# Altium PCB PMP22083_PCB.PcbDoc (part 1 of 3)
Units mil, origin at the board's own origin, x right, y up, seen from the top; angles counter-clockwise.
Board outline 6200 x 4200 mil, 2 copper layers (Top Layer, Bottom Layer), stack 62 mil thick; 186 components, 87 nets, 426 pads, 96 vias.
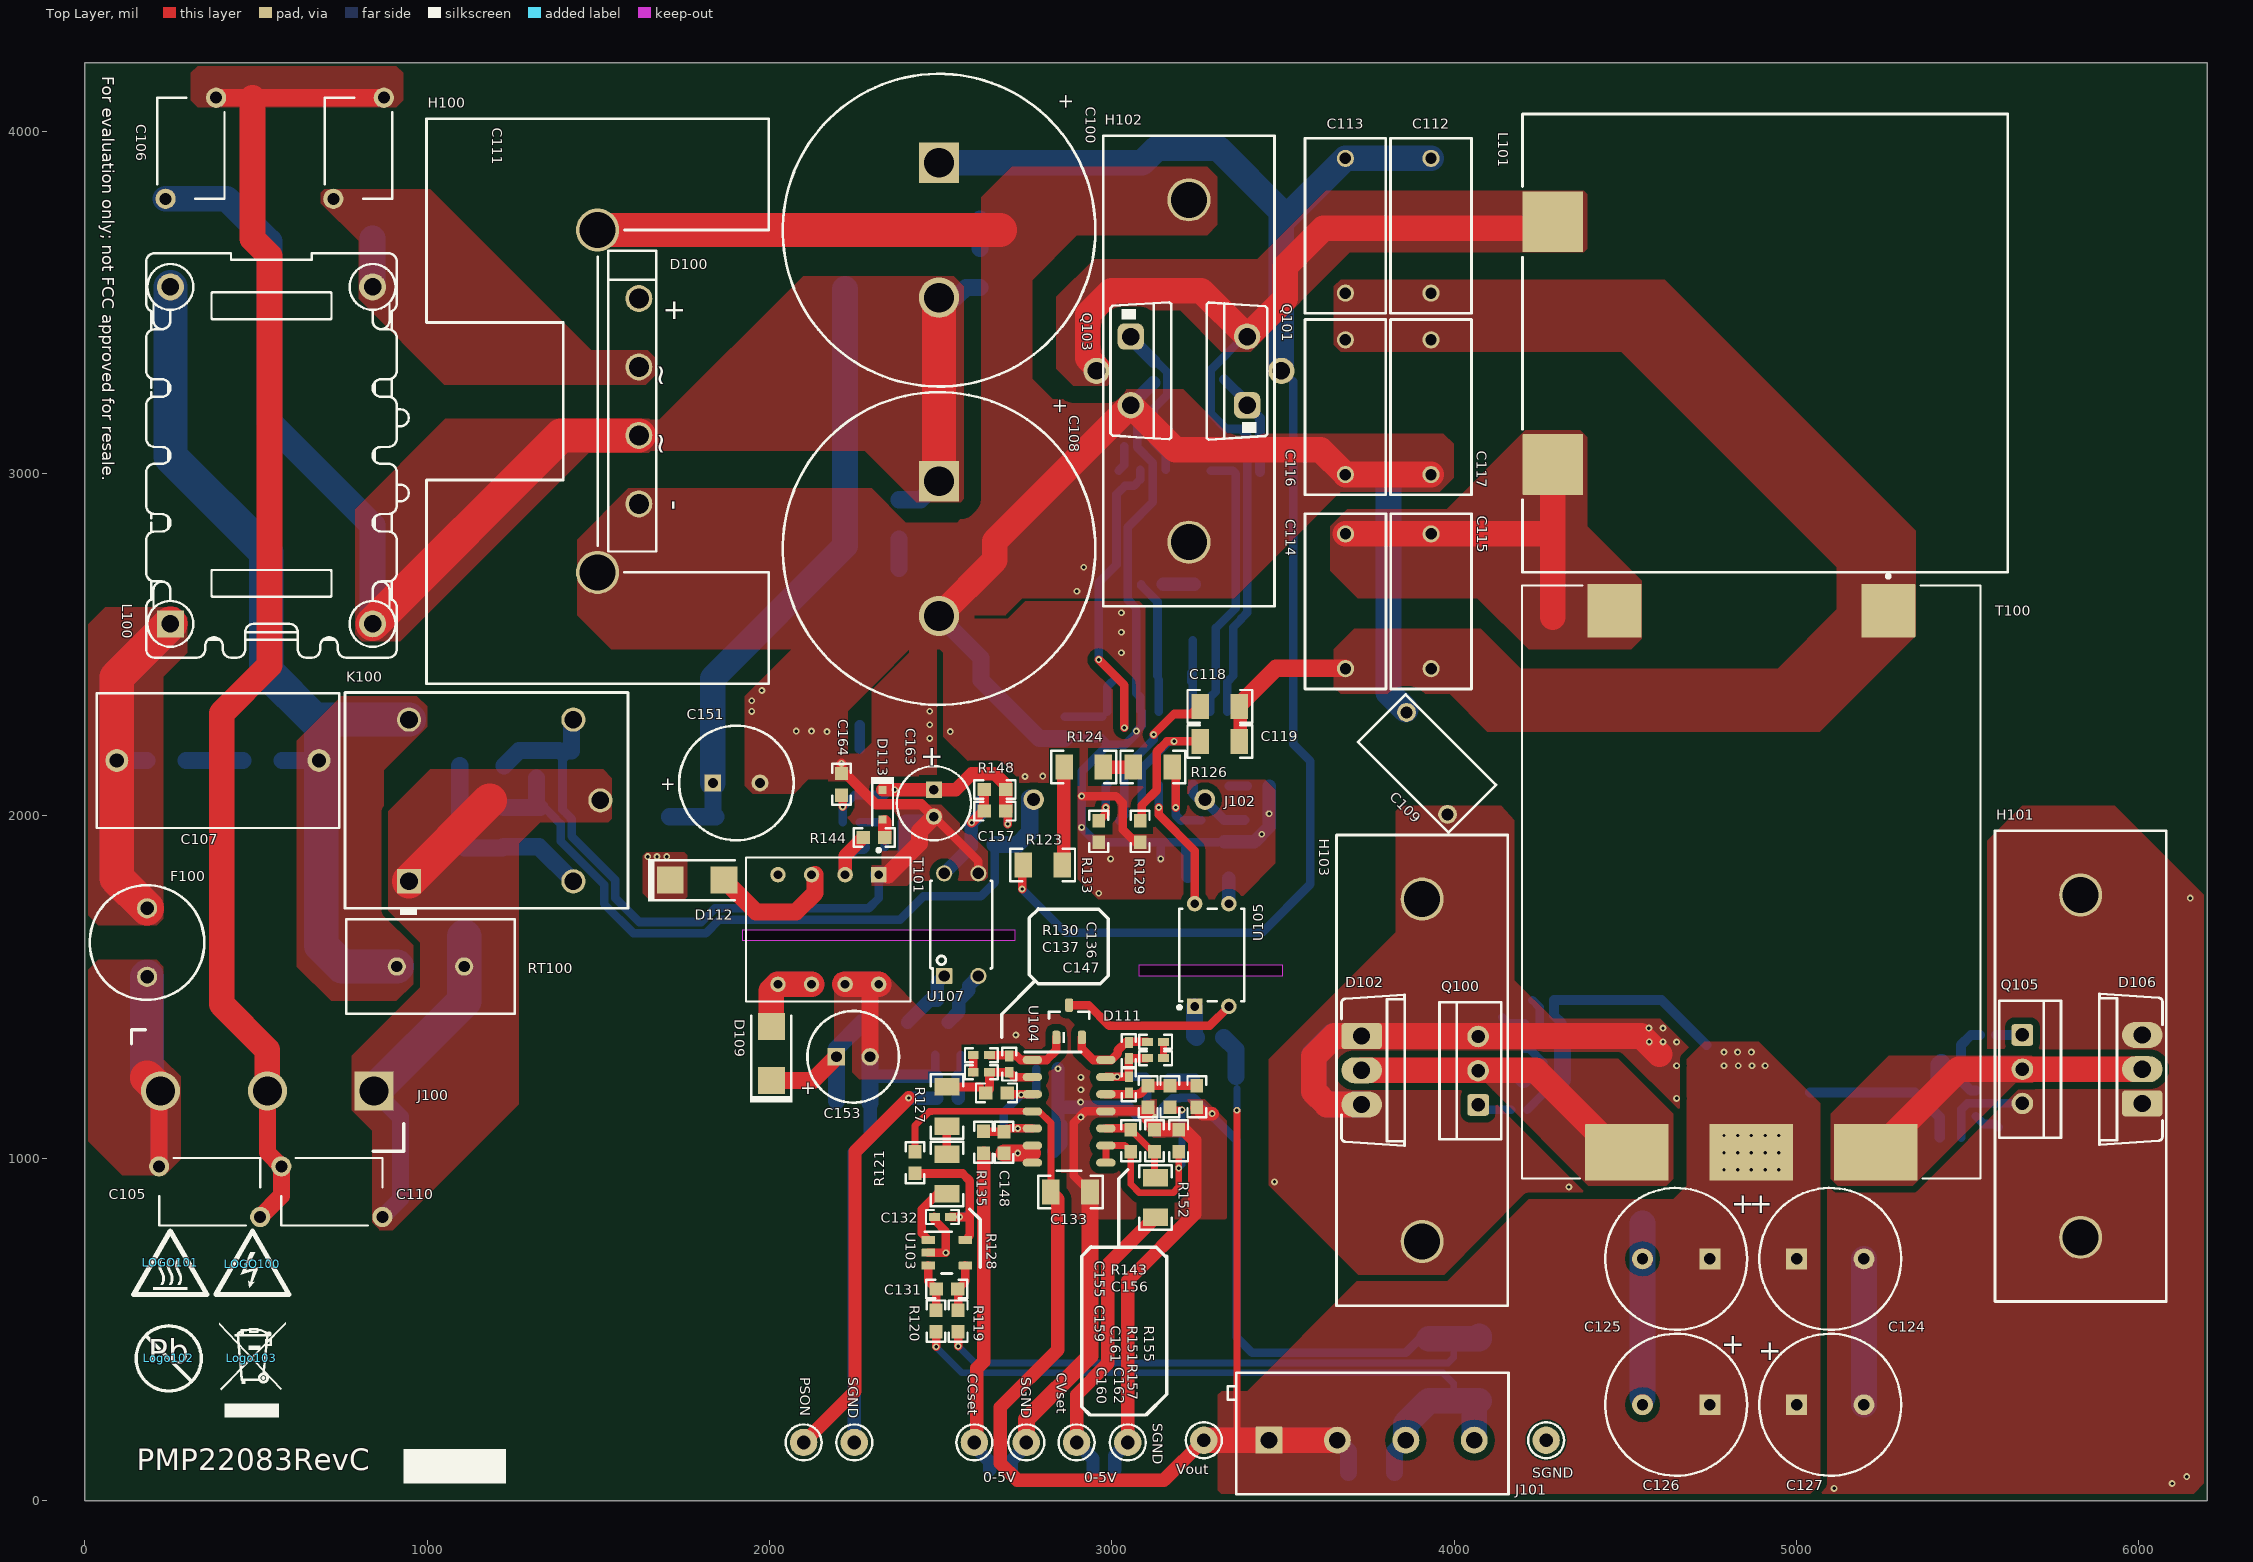
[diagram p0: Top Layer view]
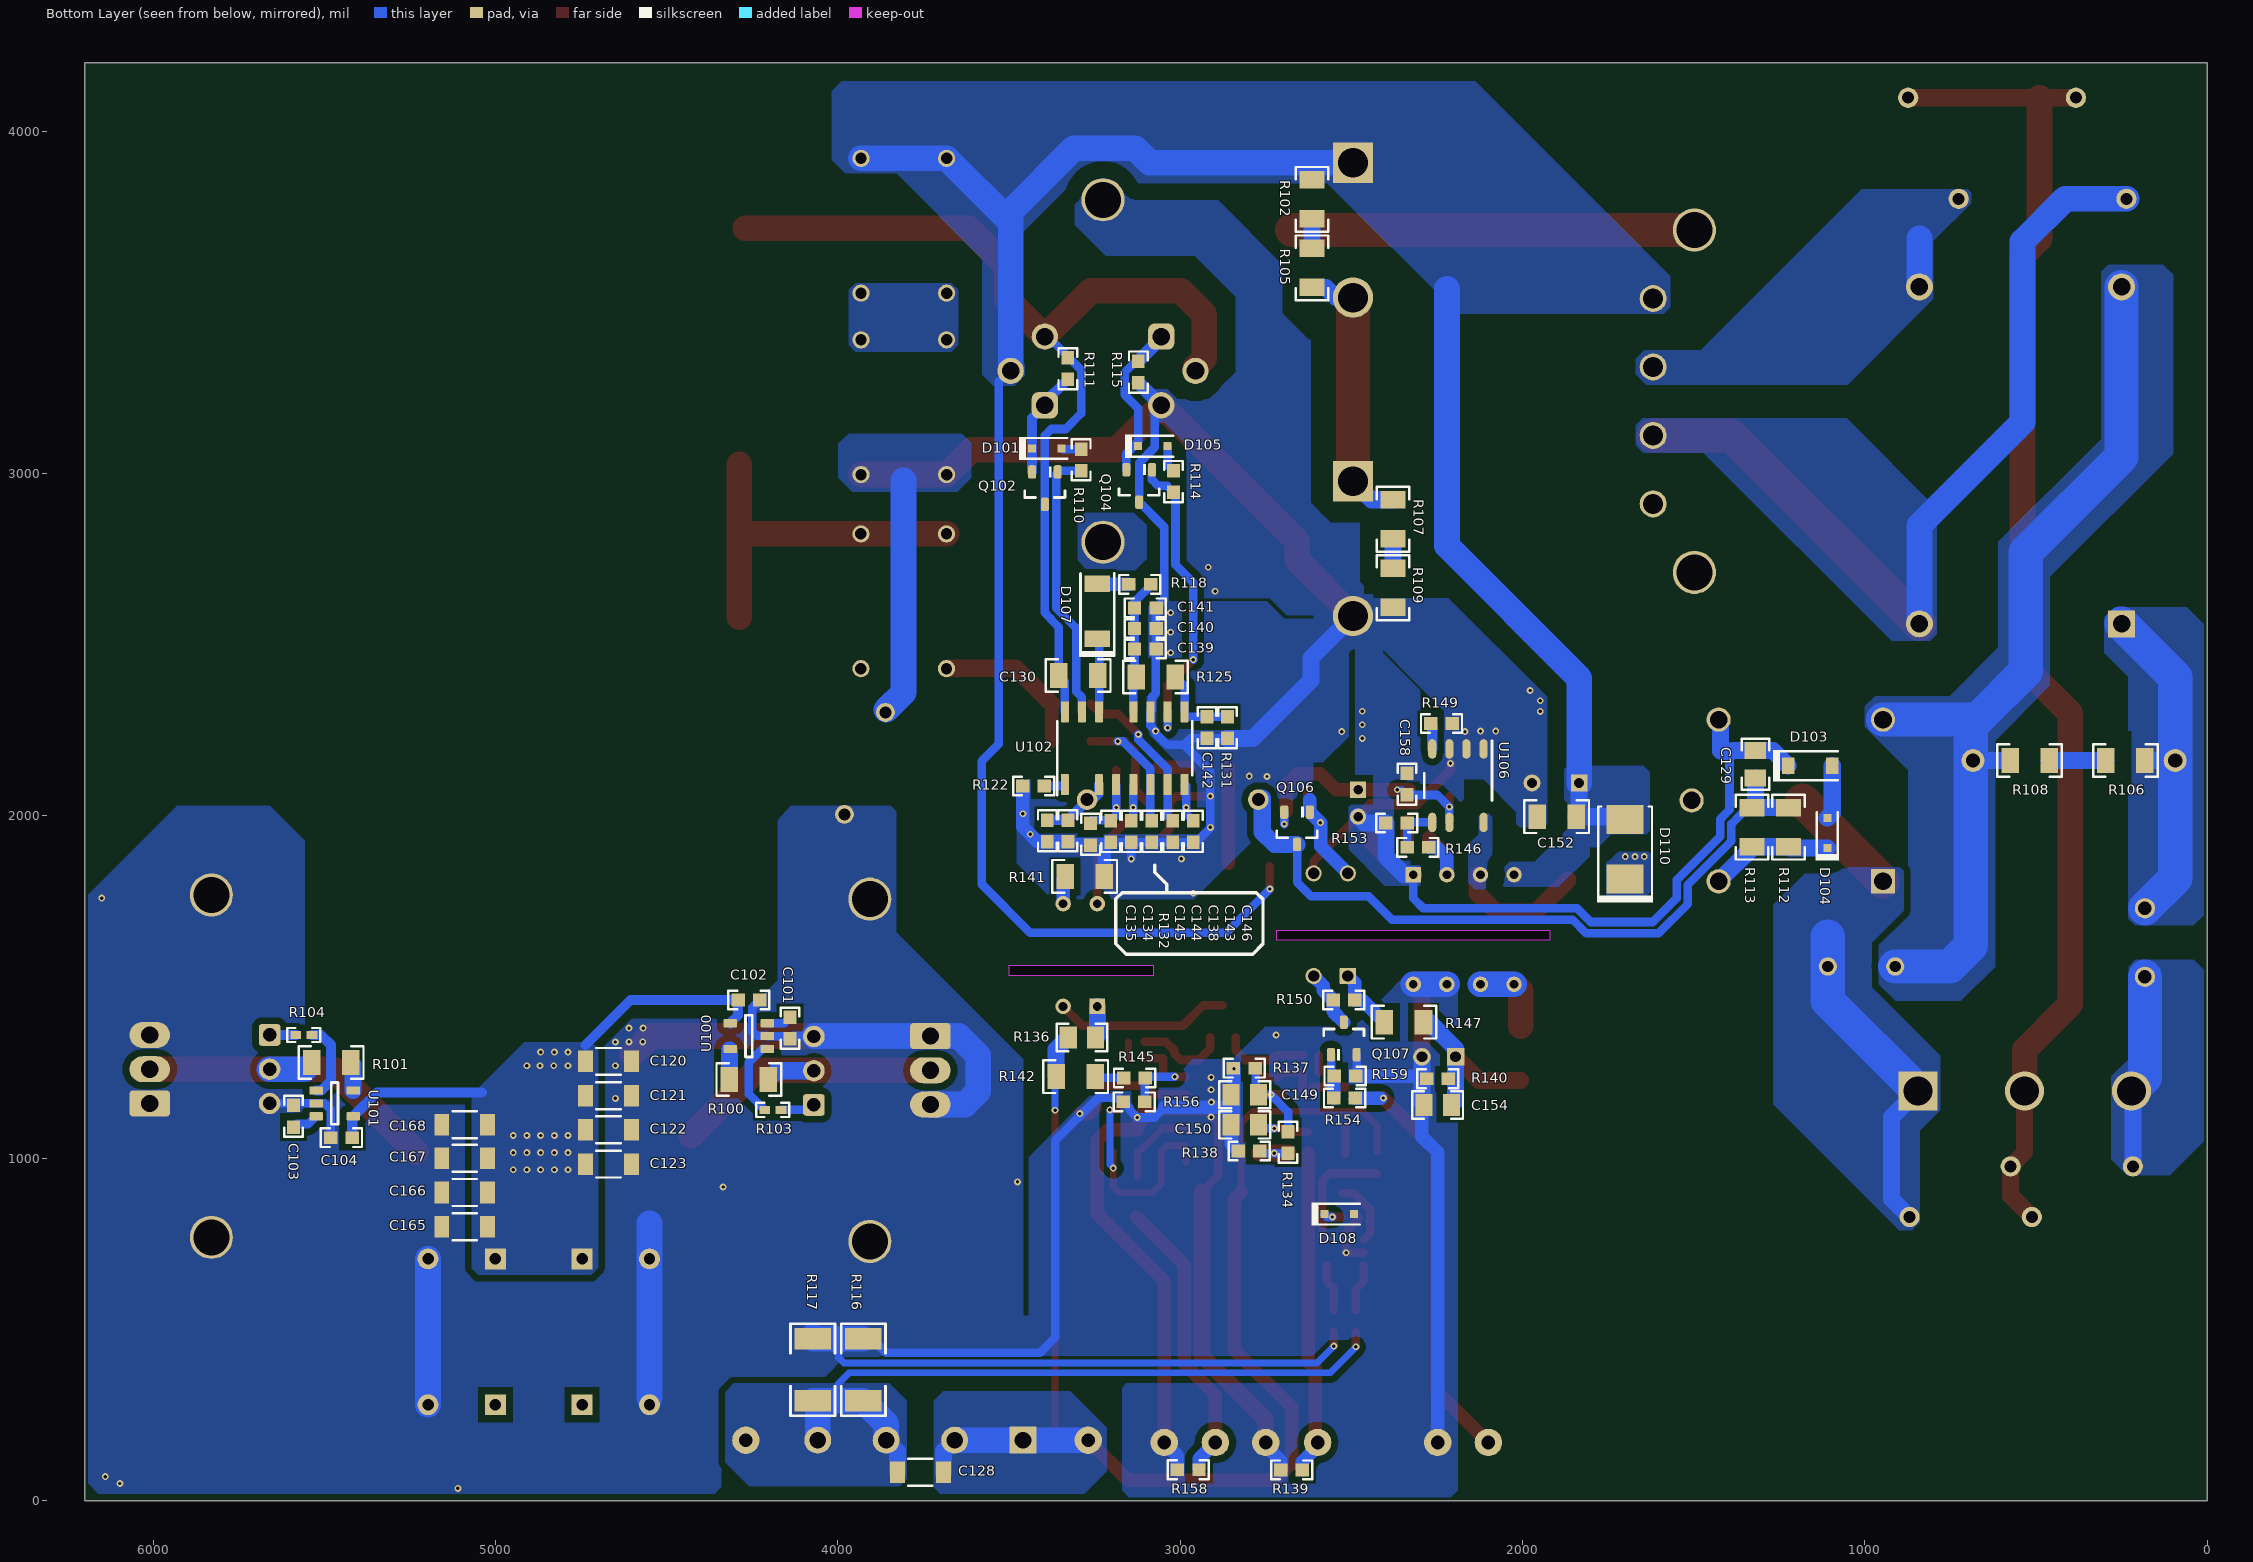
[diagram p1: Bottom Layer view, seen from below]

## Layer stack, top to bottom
Top Solder: solder mask 0.4, Solder Resist, Dk 3.5
Top Layer: signal copper 1.4
Dielectric1: core 59.2, FR-4, Dk 4.8
Bottom Layer: signal copper 1.4
Bottom Solder: solder mask 0.4, Solder Resist, Dk 3.5

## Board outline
0,0 6200,0 6200,4200 0,4200
cut-out: 1920.05,1636.33 2718.22,1636.33 2718.22,1666.33 1920.05,1666.33
cut-out: 3078.92,1533.57 3500,1533.57 3500,1563.57 3078.92,1563.57

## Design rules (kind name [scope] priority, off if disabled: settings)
AcuteAngle [All] p1: minimum=4.50000000000000E+0001 checktracksonly=FALSE
AssemblyTestPointUsage [All] p1: valid=2
Clearance Clearance_2 [InNetClass('HV') vs Not InNetClass('HV')] p1: gap=50 ignorepadtopadclearanceinfootprint=FALSE except(0: Arc-Hole Track-Hole SMDPad-Hole THPad-Hole Via-Hole Fill-Hole Poly-Hole Region-Hole Text-Hole)
Clearance Clearance_1 [InNetClass('MV') vs Not InNetClass('MV')] p2: gap=20 ignorepadtopadclearanceinfootprint=FALSE
Clearance Clearance_Keepouts [((IsTrack Or IsArc) And Not InPoly) And IsFree and IsKeepOut vs ((IsTrack Or IsArc) And Not InPoly) And IsFree and IsKeepOut] p3: gap=0 ignorepadtopadclearanceinfootprint=FALSE
Clearance Clearance_BoardEdge_MountingHoles [OnCopper and InComponentClass('Mounting Holes') vs IsKeepOut] p4: gap=40 ignorepadtopadclearanceinfootprint=FALSE except(0: Arc-Hole Track-Hole SMDPad-Hole THPad-Hole Via-Hole Fill-Hole Poly-Hole Region-Hole Text-Hole)
Clearance Clearance_BoardEdge_Poly [OnCopper and InPoly vs IsKeepOut] p5: gap=25 ignorepadtopadclearanceinfootprint=FALSE except(0: Arc-Hole Track-Hole SMDPad-Hole THPad-Hole Via-Hole Fill-Hole Poly-Hole Region-Hole Text-Hole)
Clearance Clearance_BoardEdge [OnCopper and Not InComponentClass('Logo') and not InComponentClass('FiducialMark') and not InRegion(1000,500,4000,800) and Not IsKeepout vs IsKeepOut] p6: gap=75 ignorepadtopadclearanceinfootprint=FALSE except(0: Arc-Hole Track-Hole SMDPad-Hole THPad-Hole Via-Hole Fill-Hole Poly-Hole Region-Hole Text-Hole)
Clearance Clearance_Poly [InPolygon] p7: gap=20 ignorepadtopadclearanceinfootprint=FALSE except(0: Arc-Hole Track-Hole SMDPad-Hole THPad-Hole Via-Hole Fill-Hole Poly-Hole Region-Hole Text-Hole)
Clearance [All] p8: gap=7.87 ignorepadtopadclearanceinfootprint=FALSE except(0: Arc-Hole Track-Hole SMDPad-Hole THPad-Hole Via-Hole Fill-Hole Poly-Hole Region-Hole Text-Hole)
ComponentClearance ComponentClearance_MountingHoles_FiducialMarks [InComponentClass('Mounting Holes') vs InComponentClass('FiducialMark')] p1: gap=20 collisioncheckmode=3 verticalgap=10 showdistances=FALSE
ComponentClearance ComponentClearance_Shunt [InComponentClass('Header') vs InComponentClass('Shunt')] p2: gap=0 collisioncheckmode=3 verticalgap=0 showdistances=FALSE
ComponentClearance ComponentClearance_Logo [InComponentClass('Logo')] p3: gap=5 collisioncheckmode=3 verticalgap=10 showdistances=FALSE
ComponentClearance ComponentClearance_ScrewToNut [(HasFootprint('NY PMS 440 0025 PH')) vs (HasFootprint('Keystone_1902C'))] p4: gap=20 collisioncheckmode=3 verticalgap=100000 showdistances=FALSE
ComponentClearance ComponentClearance_MountingHoles [InComponentClass('Mounting Holes')] p5: gap=20 collisioncheckmode=3 verticalgap=10 showdistances=FALSE
ComponentClearance ComponentClearance_SmallPassives [HasFootprint('0201*') or HasFootprint('0402*') or HasFootprint('0508') or HasFootprint('0603*') or HasFootprint('0612') or HasFootprint('0805*') or HasFootprint('0815*') or HasFootprint('0830*') or HasFootprint('1206*') or HasFootprint('1210*') or HasFootprint('1808*') or HasFootprint('1812*') or HasFootprint('1825*') or HasFootprint('2010*') or HasFootprint('2220*') or HasFootprint('2225*') or HasFootprint('2512*') or HasFootprint('2728*') or HasFootprint('3518*') vs HasFootprint('0201*') or HasFootprint('0402*') or HasFootprint('0508') or HasFootprint('0603*') or HasFootprint('0612') or HasFootprint('0805*') or HasFootprint('0815*') or HasFootprint('0830*') or HasFootprint('1206*') or HasFootprint('1210*') or HasFootprint('1808*') or HasFootprint('1812*') or HasFootprint('1825*') or HasFootprint('2010*') or HasFootprint('2220*') or HasFootprint('2225*') or HasFootprint('2512*') or HasFootprint('2728*') or HasFootprint('3518*')] p6: gap=20 collisioncheckmode=3 verticalgap=20 showdistances=FALSE
ComponentClearance ComponentClearance_THtoSMT [IsThruComponent vs IsSMTComponent] p7: gap=10 collisioncheckmode=3 verticalgap=10 showdistances=FALSE
ComponentClearance ComponentClearance_THtoTH [IsThruComponent vs IsThruComponent] p8: gap=10 collisioncheckmode=3 verticalgap=10 showdistances=FALSE
ComponentClearance [All] p9: gap=10 collisioncheckmode=3 verticalgap=10 showdistances=FALSE
DiffPairsRouting [All] p1: maxlimit=100 minlimit=10 mostfreqgap=10 toplayer_minwidth=15 toplayer_maxwidth=15 toplayer_prefwidth=15 bottomlayer_minwidth=15 bottomlayer_maxwidth=15 bottomlayer_prefwidth=15 maxuncoupledlength=1000
FabricationTestPointUsage TestPointUsage [All] p1: valid=2 allowmultiple=FALSE
FabricationTestpoint Testpoint [All] p1: side=3 testpointundercomponent=TRUE minsize=40 maxsize=100 preferedsize=60 minholesize=0 maxholesize=40 preferedholesize=32 testpointgrid=1 allowsidetop=TRUE allowsidebottom=TRUE usegrid=TRUE gridtolerance=0.01
FanoutControl Fanout_LCC [IsLCC] p1: bgadir=Out bgaviamode=Centered fanoutstyle=Auto fanoutdirection=Alternating viagrid=1 // Fanout_LCC (Default Rule)
FanoutControl Fanout_BGA [IsBGA] p2: bgadir=Out bgaviamode=Centered fanoutstyle=Auto fanoutdirection=Alternating viagrid=1 // Fanout_BGA (Default Rule)
FanoutControl Fanout_Default [All] p4: bgadir=Out bgaviamode=Centered fanoutstyle=Auto fanoutdirection=Alternating viagrid=1 // Fanout_Default (Default Rule)
FanoutControl Fanout_Small [(CompPinCount < 5)] p5: bgadir=Out bgaviamode=Centered fanoutstyle=Auto fanoutdirection=OutThenIn viagrid=1 // Fanout_Small (Default Rule)
Height [All] p1: minheight=0 maxheight=3000 prefheight=500
HoleSize [All] p1: absolutevalues=TRUE maxlimit=251 minlimit=7 maxpercent=80.000 minpercent=20.000
MinimumAnnularRing MinimumAnnularRing_ThermalPadVias [IsVia and InAnyComponent] p1: minimumring=5.91
MinimumAnnularRing [All] p2: minimumring=4.9
MinimumSolderMaskSliver MinimumSolderMaskSliver_Logo [InComponentClass('Logo') vs InComponentClass('Logo')] p1: minsoldermaskwidth=0.7
MinimumSolderMaskSliver [All] p2: minsoldermaskwidth=2
PlaneConnect [All] p1: planeconnectstyle=Direct reliefexpansion=10 reliefentries=4 reliefconductorwidth=10 reliefairgap=10
PolygonConnect PolygonConnect_27 [All vs IsNamedPolygon('SGND') Or  IsNamedPolygon('C110_1') Or  IsNamedPolygon('C105_2') Or  IsNamedPolygon('C105_2') Or  IsNamedPolygon('Vout') Or  IsNamedPolygon('C107_2') Or  IsNamedPolygon('C107_1') Or  IsNamedPolygon('Bottom Layer-PGND') Or  IsNamedPolygon('C124_2') Or  IsNamedPolygon('C107_1') Or  IsNamedPolygon('VD_SR2') Or  IsNamedPolygon('C100_2') Or  IsNamedPolygon('VD_SR1') Or  IsNamedPolygon('PE') Or  IsNamedPolygon('PGND') Or  IsNamedPolygon('PGND') Or  IsNamedPolygon('D110_1') Or  IsNamedPolygon('SGND') Or  IsNamedPolygon('C100_2') Or  IsNamedPolygon('PGND') Or  IsNamedPolygon('SGND') Or  IsNamedPolygon('SGND') Or  IsNamedPolygon('Vout') Or  IsNamedPolygon('C111_1') Or  IsNamedPolygon('C111_1') Or  IsNamedPolygon('C110_1') Or  IsNamedPolygon('PGND') Or  IsNamedPolygon('Vout') Or  IsNamedPolygon('D110_1') Or  IsNamedPolygon('Bottom Layer-PGND 1') Or  IsNamedPolygon('C107_2') Or  IsNamedPolygon('Vbus') Or  IsNamedPolygon('C112_2') Or  IsNamedPolygon('PGND') Or  IsNamedPolygon('C112_2') Or  IsNamedPolygon('HS') Or  IsNamedPolygon('Vbus') Or  IsNamedPolygon('C100_2') Or  IsNamedPolygon('PGND') Or  IsNamedPolygon('D108_2') Or  IsNamedPolygon('C116_1') Or  IsNamedPolygon('PGND') Or  IsNamedPolygon('PGND') Or  IsNamedPolygon('PGND')] p1: connectstyle=Direct reliefconductorwidth=10 reliefentries=4 polygonreliefangle="90 Angle" airgapwidth=10
PolygonConnect PolygonConnect_26 [All vs IsNamedPolygon('PGND') Or  IsNamedPolygon('PGND') Or  IsNamedPolygon('C124_2') Or  IsNamedPolygon('PGND') Or  IsNamedPolygon('PGND') Or  IsNamedPolygon('PGND') Or  IsNamedPolygon('SGND') Or  IsNamedPolygon('Vout') Or  IsNamedPolygon('SGND') Or  IsNamedPolygon('Bottom Layer-PGND') Or  IsNamedPolygon('SGND') Or  IsNamedPolygon('Bottom Layer-PGND 1') Or  IsNamedPolygon('Vout') Or  IsNamedPolygon('VD_SR1') Or  IsNamedPolygon('VD_SR2') Or  IsNamedPolygon('D110_1') Or  IsNamedPolygon('D110_1') Or  IsNamedPolygon('Vout') Or  IsNamedPolygon('SGND') Or  IsNamedPolygon('C107_1') Or  IsNamedPolygon('C110_1') Or  IsNamedPolygon('C110_1') Or  IsNamedPolygon('PGND') Or  IsNamedPolygon('D108_2') Or  IsNamedPolygon('C112_2') Or  IsNamedPolygon('HS') Or  IsNamedPolygon('PGND') Or  IsNamedPolygon('C100_2') Or  IsNamedPolygon('PGND') Or  IsNamedPolygon('PGND') Or  IsNamedPolygon('Vbus') Or  IsNamedPolygon('C112_2') Or  IsNamedPolygon('Vbus') Or  IsNamedPolygon('C116_1')] p2: connectstyle=Direct reliefconductorwidth=10 reliefentries=4 polygonreliefangle="90 Angle" airgapwidth=10
PolygonConnect PolygonConnect_25 [All vs IsNamedPolygon('Vout')] p3: connectstyle=Direct reliefconductorwidth=10 reliefentries=4 polygonreliefangle="90 Angle" airgapwidth=10
PolygonConnect PolygonConnect_24 [All vs IsNamedPolygon('C116_1') Or  IsNamedPolygon('PGND') Or  IsNamedPolygon('HS') Or  IsNamedPolygon('PGND') Or  IsNamedPolygon('D108_2') Or  IsNamedPolygon('C112_2') Or  IsNamedPolygon('C100_2') Or  IsNamedPolygon('Vbus') Or  IsNamedPolygon('PGND') Or  IsNamedPolygon('PGND') Or  IsNamedPolygon('PGND') Or  IsNamedPolygon('VD_SR1') Or  IsNamedPolygon('D110_1') Or  IsNamedPolygon('Bottom Layer-PGND 1') Or  IsNamedPolygon('PGND') Or  IsNamedPolygon('Vout') Or  IsNamedPolygon('VD_SR2') Or  IsNamedPolygon('PGND') Or  IsNamedPolygon('PGND') Or  IsNamedPolygon('D110_1') Or  IsNamedPolygon('Bottom Layer-PGND') Or  IsNamedPolygon('Vbus') Or  IsNamedPolygon('PGND') Or  IsNamedPolygon('C124_2') Or  IsNamedPolygon('C112_2')] p4: connectstyle=Direct reliefconductorwidth=10 reliefentries=4 polygonreliefangle="90 Angle" airgapwidth=10
PolygonConnect PolygonConnect_23 [All vs IsNamedPolygon('Bottom Layer-PGND 1') Or  IsNamedPolygon('D110_1') Or  IsNamedPolygon('D110_1') Or  IsNamedPolygon('C112_2') Or  IsNamedPolygon('D108_2') Or  IsNamedPolygon('HS') Or  IsNamedPolygon('Vbus') Or  IsNamedPolygon('C124_2') Or  IsNamedPolygon('PGND') Or  IsNamedPolygon('C100_2') Or  IsNamedPolygon('PGND') Or  IsNamedPolygon('PGND') Or  IsNamedPolygon('C112_2') Or  IsNamedPolygon('PGND') Or  IsNamedPolygon('PGND') Or  IsNamedPolygon('Bottom Layer-PGND') Or  IsNamedPolygon('PGND') Or  IsNamedPolygon('PGND') Or  IsNamedPolygon('C116_1') Or  IsNamedPolygon('PGND') Or  IsNamedPolygon('PGND') Or  IsNamedPolygon('Vbus')] p5: connectstyle=Direct reliefconductorwidth=10 reliefentries=4 polygonreliefangle="90 Angle" airgapwidth=10
PolygonConnect PolygonConnect_22 [All vs IsNamedPolygon('C116_1') Or  IsNamedPolygon('Vbus') Or  IsNamedPolygon('PGND') Or  IsNamedPolygon('SGND') Or  IsNamedPolygon('C112_2') Or  IsNamedPolygon('D108_2') Or  IsNamedPolygon('Vout') Or  IsNamedPolygon('PGND') Or  IsNamedPolygon('PGND') Or  IsNamedPolygon('PGND') Or  IsNamedPolygon('C107_2') Or  IsNamedPolygon('Vout') Or  IsNamedPolygon('PE') Or  IsNamedPolygon('C111_1') Or  IsNamedPolygon('PGND') Or  IsNamedPolygon('Vbus') Or  IsNamedPolygon('SGND') Or  IsNamedPolygon('SGND') Or  IsNamedPolygon('SGND') Or  IsNamedPolygon('PGND') Or  IsNamedPolygon('C107_2') Or  IsNamedPolygon('D105_1') Or  IsNamedPolygon('D104_1') Or  IsNamedPolygon('HS') Or  IsNamedPolygon('C100_2') Or  IsNamedPolygon('Vout') Or  IsNamedPolygon('D104_1') Or  IsNamedPolygon('D105_1') Or  IsNamedPolygon('SGND') Or  IsNamedPolygon('SGND') Or  IsNamedPolygon('C100_2') Or  IsNamedPolygon('C101_2') Or  IsNamedPolygon('PGND') Or  IsNamedPolygon('PE') Or  IsNamedPolygon('C124_2') Or  IsNamedPolygon('PGND') Or  IsNamedPolygon('C112_2') Or  IsNamedPolygon('C101_2') Or  IsNamedPolygon('PGND') Or  IsNamedPolygon('Bottom Layer-PGND') Or  IsNamedPolygon('Bottom Layer-PGND 1')] p6: connectstyle=Direct reliefconductorwidth=10 reliefentries=4 polygonreliefangle="90 Angle" airgapwidth=10
PolygonConnect PolygonConnect_21 [All vs IsNamedPolygon('SGND') Or  IsNamedPolygon('PGND') Or  IsNamedPolygon('PGND') Or  IsNamedPolygon('SGND') Or  IsNamedPolygon('SGND') Or  IsNamedPolygon('Vout') Or  IsNamedPolygon('C124_2') Or  IsNamedPolygon('PGND') Or  IsNamedPolygon('Vout') Or  IsNamedPolygon('PGND') Or  IsNamedPolygon('D105_1') Or  IsNamedPolygon('SGND') Or  IsNamedPolygon('D104_1') Or  IsNamedPolygon('Vout') Or  IsNamedPolygon('Bottom Layer-PGND') Or  IsNamedPolygon('SGND') Or  IsNamedPolygon('PGND') Or  IsNamedPolygon('PGND') Or  IsNamedPolygon('PGND') Or  IsNamedPolygon('SGND') Or  IsNamedPolygon('PGND') Or  IsNamedPolygon('C112_2') Or  IsNamedPolygon('C101_2') Or  IsNamedPolygon('C107_2') Or  IsNamedPolygon('C107_2') Or  IsNamedPolygon('D105_1') Or  IsNamedPolygon('C112_2') Or  IsNamedPolygon('Vbus') Or  IsNamedPolygon('HS') Or  IsNamedPolygon('C116_1') Or  IsNamedPolygon('PGND') Or  IsNamedPolygon('C100_2') Or  IsNamedPolygon('D108_2') Or  IsNamedPolygon('C101_2') Or  IsNamedPolygon('C100_2') Or  IsNamedPolygon('D104_1') Or  IsNamedPolygon('Vbus') Or  IsNamedPolygon('C111_1') Or  IsNamedPolygon('PE') Or  IsNamedPolygon('PE')] p7: connectstyle=Direct reliefconductorwidth=10 reliefentries=4 polygonreliefangle="90 Angle" airgapwidth=10
PolygonConnect PolygonConnect_20 [All vs IsNamedPolygon('Vout') Or  IsNamedPolygon('Vout') Or  IsNamedPolygon('Vbus') Or  IsNamedPolygon('Vout') Or  IsNamedPolygon('C101_2') Or  IsNamedPolygon('C107_2') Or  IsNamedPolygon('C124_2') Or  IsNamedPolygon('PGND') Or  IsNamedPolygon('SGND') Or  IsNamedPolygon('C112_2') Or  IsNamedPolygon('D104_1') Or  IsNamedPolygon('D105_1') Or  IsNamedPolygon('PGND') Or  IsNamedPolygon('PGND') Or  IsNamedPolygon('PGND') Or  IsNamedPolygon('HS') Or  IsNamedPolygon('C100_2') Or  IsNamedPolygon('SGND') Or  IsNamedPolygon('C100_2') Or  IsNamedPolygon('C101_2') Or  IsNamedPolygon('PE') Or  IsNamedPolygon('C116_1') Or  IsNamedPolygon('PGND') Or  IsNamedPolygon('C111_1') Or  IsNamedPolygon('D108_2') Or  IsNamedPolygon('C112_2') Or  IsNamedPolygon('C107_2') Or  IsNamedPolygon('Vbus') Or  IsNamedPolygon('PE') Or  IsNamedPolygon('D104_1') Or  IsNamedPolygon('D105_1') Or  IsNamedPolygon('PGND') Or  IsNamedPolygon('PGND') Or  IsNamedPolygon('PGND') Or  IsNamedPolygon('PGND')] p8: connectstyle=Direct reliefconductorwidth=10 reliefentries=4 polygonreliefangle="90 Angle" airgapwidth=10
PolygonConnect PolygonConnect_19 [All vs IsNamedPolygon('PE') Or  IsNamedPolygon('PE') Or  IsNamedPolygon('C101_2') Or  IsNamedPolygon('C101_2') Or  IsNamedPolygon('C107_2') Or  IsNamedPolygon('C107_2') Or  IsNamedPolygon('C100_2') Or  IsNamedPolygon('C111_1') Or  IsNamedPolygon('Vbus') Or  IsNamedPolygon('Vbus') Or  IsNamedPolygon('D108_2') Or  IsNamedPolygon('PGND')] p9: connectstyle=Direct reliefconductorwidth=10 reliefentries=4 polygonreliefangle="90 Angle" airgapwidth=10
PolygonConnect PolygonConnect_18 [All vs IsNamedPolygon('Vbus') Or  IsNamedPolygon('PGND') Or  IsNamedPolygon('Vout') Or  IsNamedPolygon('PGND') Or  IsNamedPolygon('C112_2') Or  IsNamedPolygon('C116_1') Or  IsNamedPolygon('HS') Or  IsNamedPolygon('C124_2') Or  IsNamedPolygon('5V') Or  IsNamedPolygon('C107_2') Or  IsNamedPolygon('C124_2') Or  IsNamedPolygon('PGND') Or  IsNamedPolygon('Vbus') Or  IsNamedPolygon('PGND') Or  IsNamedPolygon('C107_2') Or  IsNamedPolygon('VD_SR2') Or  IsNamedPolygon('Vout') Or  IsNamedPolygon('VD_SR_1') Or  IsNamedPolygon('C101_2') Or  IsNamedPolygon('PE') Or  IsNamedPolygon('VD_SR_1') Or  IsNamedPolygon('Vout') Or  IsNamedPolygon('C100_2') Or  IsNamedPolygon('D106_2') Or  IsNamedPolygon('VD_SR2') Or  IsNamedPolygon('PE') Or  IsNamedPolygon('PGND') Or  IsNamedPolygon('C112_2') Or  IsNamedPolygon('PE') Or  IsNamedPolygon('C100_2') Or  IsNamedPolygon('Vbus') Or  IsNamedPolygon('PE') Or  IsNamedPolygon('C101_2')] p10: connectstyle=Direct reliefconductorwidth=10 reliefentries=4 polygonreliefangle="90 Angle" airgapwidth=10
PolygonConnect PolygonConnect_17 [All vs IsNamedPolygon('PGND') Or  IsNamedPolygon('Vout') Or  IsNamedPolygon('C116_1') Or  IsNamedPolygon('C100_2') Or  IsNamedPolygon('C124_2') Or  IsNamedPolygon('C112_2') Or  IsNamedPolygon('C107_2') Or  IsNamedPolygon('PE') Or  IsNamedPolygon('HS') Or  IsNamedPolygon('Vbus') Or  IsNamedPolygon('PE') Or  IsNamedPolygon('PGND') Or  IsNamedPolygon('VD_SR_1') Or  IsNamedPolygon('VD_SR_1') Or  IsNamedPolygon('C100_2') Or  IsNamedPolygon('Vbus') Or  IsNamedPolygon('Vout') Or  IsNamedPolygon('VD_SR2') Or  IsNamedPolygon('C101_2') Or  IsNamedPolygon('C107_2') Or  IsNamedPolygon('C112_2') Or  IsNamedPolygon('VD_SR2') Or  IsNamedPolygon('C101_2')] p11: connectstyle=Direct reliefconductorwidth=10 reliefentries=4 polygonreliefangle="90 Angle" airgapwidth=10
PolygonConnect PolygonConnect_16 [All vs IsNamedPolygon('Vout') Or  IsNamedPolygon('VD_SR2') Or  IsNamedPolygon('VD_SR_1') Or  IsNamedPolygon('PE') Or  IsNamedPolygon('VD_SR2') Or  IsNamedPolygon('VD_SR_1') Or  IsNamedPolygon('C112_2')] p12: connectstyle=Direct reliefconductorwidth=10 reliefentries=4 polygonreliefangle="90 Angle" airgapwidth=10
PolygonConnect PolygonConnect_15 [All vs IsNamedPolygon('C109_2') Or  IsNamedPolygon('C107_2') Or  IsNamedPolygon('HV') Or  IsNamedPolygon('Q203_5') Or  IsNamedPolygon('C107_2') Or  IsNamedPolygon('HS') Or  IsNamedPolygon('Q201_5') Or  IsNamedPolygon('Q203_5') Or  IsNamedPolygon('C106_2') Or  IsNamedPolygon('C108_2') Or  IsNamedPolygon('Vout') Or  IsNamedPolygon('Q203_5') Or  IsNamedPolygon('C108_2') Or  IsNamedPolygon('C113_2') Or  IsNamedPolygon('Q203_5') Or  IsNamedPolygon('Q201_5') Or  IsNamedPolygon('C107_2') Or  IsNamedPolygon('C102_1') Or  IsNamedPolygon('PE') Or  IsNamedPolygon('GND') Or  IsNamedPolygon('PE') Or  IsNamedPolygon('GND') Or  IsNamedPolygon('IN+') Or  IsNamedPolygon('IN+') Or  IsNamedPolygon('Q201_5') Or  IsNamedPolygon('Q201_5') Or  IsNamedPolygon('PE') Or  IsNamedPolygon('PE') Or  IsNamedPolygon('Vout') Or  IsNamedPolygon('Vout') Or  IsNamedPolygon('IN+') Or  IsNamedPolygon('GND') Or  IsNamedPolygon('IN+') Or  IsNamedPolygon('GND')] p13: connectstyle=Direct reliefconductorwidth=10 reliefentries=4 polygonreliefangle="90 Angle" airgapwidth=10
PolygonConnect PolygonConnect_14 [All vs IsNamedPolygon('C106_2') Or  IsNamedPolygon('C107_2') Or  IsNamedPolygon('C107_2') Or  IsNamedPolygon('C107_2') Or  IsNamedPolygon('C102_1') Or  IsNamedPolygon('Q203_5') Or  IsNamedPolygon('Vout') Or  IsNamedPolygon('Q203_5') Or  IsNamedPolygon('Q203_5') Or  IsNamedPolygon('Q201_5') Or  IsNamedPolygon('C108_2') Or  IsNamedPolygon('Q203_5') Or  IsNamedPolygon('HS') Or  IsNamedPolygon('HV') Or  IsNamedPolygon('C108_2') Or  IsNamedPolygon('Q201_5') Or  IsNamedPolygon('C109_2') Or  IsNamedPolygon('Q201_5') Or  IsNamedPolygon('Q201_5') Or  IsNamedPolygon('C113_2')] p14: connectstyle=Direct reliefconductorwidth=10 reliefentries=4 polygonreliefangle="90 Angle" airgapwidth=10
PolygonConnect PolygonConnect_13 [All vs IsNamedPolygon('C102_1') Or  IsNamedPolygon('HV') Or  IsNamedPolygon('C107_2') Or  IsNamedPolygon('C109_2') Or  IsNamedPolygon('C107_2') Or  IsNamedPolygon('C108_2') Or  IsNamedPolygon('C106_2') Or  IsNamedPolygon('C108_2') Or  IsNamedPolygon('C113_2') Or  IsNamedPolygon('C107_2')] p15: connectstyle=Direct reliefconductorwidth=10 reliefentries=4 polygonreliefangle="90 Angle" airgapwidth=10
PolygonConnect PolygonConnect_12 [All vs IsNamedPolygon('C107_2') Or  IsNamedPolygon('C113_2') Or  IsNamedPolygon('C106_2') Or  IsNamedPolygon('C107_2') Or  IsNamedPolygon('C107_2') Or  IsNamedPolygon('C102_1')] p16: connectstyle=Direct reliefconductorwidth=10 reliefentries=4 polygonreliefangle="90 Angle" airgapwidth=10
PolygonConnect PolygonConnect_11 [All vs IsNamedPolygon('C106_2') Or  IsNamedPolygon('C102_1') Or  IsNamedPolygon('C107_2') Or  IsNamedPolygon('C107_2') Or  IsNamedPolygon('C107_2')] p17: connectstyle=Direct reliefconductorwidth=10 reliefentries=4 polygonreliefangle="90 Angle" airgapwidth=10
PolygonConnect PolygonConnect_10 [All vs IsNamedPolygon('C106_2')] p18: connectstyle=Direct reliefconductorwidth=10 reliefentries=4 polygonreliefangle="90 Angle" airgapwidth=10
PolygonConnect PolygonConnect_9 [All vs IsNamedPolygon('C11_1') Or  IsNamedPolygon('Vin') Or  IsNamedPolygon('Vin') Or  IsNamedPolygon('5V') Or  IsNamedPolygon('D6_2') Or  IsNamedPolygon('Q3_3') Or  IsNamedPolygon('GND2') Or  IsNamedPolygon('GND2') Or  IsNamedPolygon('GND') Or  IsNamedPolygon('Q3_4') Or  IsNamedPolygon('12V5') Or  IsNamedPolygon('GND') Or  IsNamedPolygon('12V5') Or  IsNamedPolygon('D3_1')] p19: connectstyle=Direct reliefconductorwidth=10 reliefentries=4 polygonreliefangle="90 Angle" airgapwidth=10
PolygonConnect PolygonConnect_8 [All vs IsNamedPolygon('C11_1') Or  IsNamedPolygon('Vin') Or  IsNamedPolygon('12V5') Or  IsNamedPolygon('Q3_3') Or  IsNamedPolygon('GND2') Or  IsNamedPolygon('GND2') Or  IsNamedPolygon('5V') Or  IsNamedPolygon('Q3_4') Or  IsNamedPolygon('12V5')] p20: connectstyle=Direct reliefconductorwidth=10 reliefentries=4 polygonreliefangle="90 Angle" airgapwidth=10
PolygonConnect PolygonConnect_7 [All vs IsNamedPolygon('GND2') Or  IsNamedPolygon('GND2') Or  IsNamedPolygon('5V') Or  IsNamedPolygon('12V5') Or  IsNamedPolygon('12V5') Or  IsNamedPolygon('C11_1')] p21: connectstyle=Direct reliefconductorwidth=10 reliefentries=4 polygonreliefangle="90 Angle" airgapwidth=10
PolygonConnect PolygonConnect_6 [All vs IsNamedPolygon('GND2') Or  IsNamedPolygon('PE') Or  IsNamedPolygon('GND1') Or  IsNamedPolygon('C901_1') Or  IsNamedPolygon('PE') Or  IsNamedPolygon('GND2') Or  IsNamedPolygon('GND1')] p22: connectstyle=Direct reliefconductorwidth=10 reliefentries=4 polygonreliefangle="90 Angle" airgapwidth=10
PolygonConnect PolygonConnect_5 [All vs IsNamedPolygon('GND1') Or  IsNamedPolygon('GND1')] p23: connectstyle=Direct reliefconductorwidth=10 reliefentries=4 polygonreliefangle="90 Angle" airgapwidth=10
PolygonConnect PolygonConnect_4 [All vs IsNamedPolygon('C21_1') Or  IsNamedPolygon('C5_1') Or  IsNamedPolygon('C12_2') Or  IsNamedPolygon('C2_2') Or  IsNamedPolygon('C13_1') Or  IsNamedPolygon('C28_1') Or  IsNamedPolygon('C6_1') Or  IsNamedPolygon('GND') Or  IsNamedPolygon('GND2') Or  IsNamedPolygon('C14_1') Or  IsNamedPolygon('C13_1') Or  IsNamedPolygon('Q1_3') Or  IsNamedPolygon('C14_1') Or  IsNamedPolygon('C5_1') Or  IsNamedPolygon('GND2') Or  IsNamedPolygon('C28_1') Or  IsNamedPolygon('D5_2') Or  IsNamedPolygon('D6_2') Or  IsNamedPolygon('D2_1') Or  IsNamedPolygon('C12_2') Or  IsNamedPolygon('D2_1') Or  IsNamedPolygon('C4_1') Or  IsNamedPolygon('C4_1') Or  IsNamedPolygon('C2_2') Or  IsNamedPolygon('GND') Or  IsNamedPolygon('C33_1') Or  IsNamedPolygon('C9_1')] p24: connectstyle=Direct reliefconductorwidth=10 reliefentries=4 polygonreliefangle="90 Angle" airgapwidth=10
PolygonConnect PolygonConnect_3 [All vs IsNamedPolygon('C28_1') Or  IsNamedPolygon('C12_2') Or  IsNamedPolygon('C28_1') Or  IsNamedPolygon('C9_1') Or  IsNamedPolygon('D5_2') Or  IsNamedPolygon('C12_2') Or  IsNamedPolygon('C2_2') Or  IsNamedPolygon('C14_1') Or  IsNamedPolygon('C4_1') Or  IsNamedPolygon('C14_1') Or  IsNamedPolygon('D6_2') Or  IsNamedPolygon('GND2') Or  IsNamedPolygon('Q1_3') Or  IsNamedPolygon('C5_1') Or  IsNamedPolygon('D2_1') Or  IsNamedPolygon('C4_1') Or  IsNamedPolygon('C13_1') Or  IsNamedPolygon('C5_1') Or  IsNamedPolygon('C13_1') Or  IsNamedPolygon('C33_1') Or  IsNamedPolygon('D2_1') Or  IsNamedPolygon('GND') Or  IsNamedPolygon('GND') Or  IsNamedPolygon('GND2') Or  IsNamedPolygon('C2_2') Or  IsNamedPolygon('C6_1') Or  IsNamedPolygon('C21_1')] p25: connectstyle=Direct reliefconductorwidth=10 reliefentries=4 polygonreliefangle="90 Angle" airgapwidth=10
PolygonConnect PolygonConnect_2 [All vs IsNamedPolygon('C21_1') Or  IsNamedPolygon('C4_1') Or  IsNamedPolygon('D5_2') Or  IsNamedPolygon('C5_1') Or  IsNamedPolygon('C14_1') Or  IsNamedPolygon('C13_1') Or  IsNamedPolygon('C4_1') Or  IsNamedPolygon('C33_1') Or  IsNamedPolygon('C12_2') Or  IsNamedPolygon('D2_1') Or  IsNamedPolygon('C2_2') Or  IsNamedPolygon('C28_1') Or  IsNamedPolygon('C12_2') Or  IsNamedPolygon('D2_1') Or  IsNamedPolygon('C5_1') Or  IsNamedPolygon('Q1_3') Or  IsNamedPolygon('GND') Or  IsNamedPolygon('D6_2') Or  IsNamedPolygon('C6_1') Or  IsNamedPolygon('C2_2') Or  IsNamedPolygon('C14_1') Or  IsNamedPolygon('C28_1') Or  IsNamedPolygon('C13_1') Or  IsNamedPolygon('C9_1') Or  IsNamedPolygon('GND')] p26: connectstyle=Direct reliefconductorwidth=10 reliefentries=4 polygonreliefangle="90 Angle" airgapwidth=10
PolygonConnect PolygonConnect_1 [All vs IsNamedPolygon('C28_1') Or  IsNamedPolygon('D5_2') Or  IsNamedPolygon('C5_1') Or  IsNamedPolygon('C5_1') Or  IsNamedPolygon('D2_1') Or  IsNamedPolygon('C21_1') Or  IsNamedPolygon('C9_1') Or  IsNamedPolygon('C4_1') Or  IsNamedPolygon('C14_1') Or  IsNamedPolygon('C28_1') Or  IsNamedPolygon('C6_1') Or  IsNamedPolygon('C12_2') Or  IsNamedPolygon('C33_1') Or  IsNamedPolygon('C4_1') Or  IsNamedPolygon('C13_1') Or  IsNamedPolygon('C12_2') Or  IsNamedPolygon('D6_2') Or  IsNamedPolygon('C2_2') Or  IsNamedPolygon('C14_1') Or  IsNamedPolygon('D2_1') Or  IsNamedPolygon('C2_2') Or  IsNamedPolygon('C13_1')] p27: connectstyle=Direct reliefconductorwidth=10 reliefentries=4 polygonreliefangle="90 Angle" airgapwidth=10
PolygonConnect [All] p28: connectstyle=Relief reliefconductorwidth=10 reliefentries=4 polygonreliefangle="90 Angle" airgapwidth=10
RoutingVias ThermalPadVias [IsVia and InAnyComponent] p1: holewidth=7.87 width=19.68 viastyle="Through Hole" minholewidth=7.87 minwidth=19.68 maxholewidth=12.99 maxwidth=23.62
RoutingVias [All] p2: holewidth=16 width=34 viastyle="Through Hole" minholewidth=7.87 minwidth=20 maxholewidth=40 maxwidth=65
SilkToBoardRegionClearance [Not ((IsComment or IsDesignator) And (Hide <> 'False')) and not InRegion(1000,500,4000,800)] p1:
SilkToSilkClearance SilkToSilkClearance_Pb-FreeLogo [(HasFootprint('Pb-Free_Overlay_Medium') OR HasFootprint('Pb-Free_Overlay_Small')) vs (HasFootprint('Pb-Free_Overlay_Medium') OR HasFootprint('Pb-Free_Overlay_Small'))] p1: silktosilkclearance=0
SilkToSilkClearance [All] p2: silktosilkclearance=1
SilkToSolderMaskClearance "Silk to Solder Mask Opening" [All] p1: minsilkscreentomaskgap=1 clearancetoexposedcopper=FALSE
SolderMaskExpansion [All] p1: expansion=1.97
Width [All] p1: maxlimit=100 minlimit=6 preferedwidth=10 checkconnectedcopper=TRUE
14 further rules are at their usual default settings.

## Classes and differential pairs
net class HV: HO HS NetC100_2 NetC105_2 NetC107_1 NetC107_2 NetC110_1 NetC111_1 NetC112_2 NetC114_1 NetC130_1 NetD101_1 NetD101_2 NetR102_1 NetR107_1 Vbus
net class MV: NetR123_1 NetR124_1

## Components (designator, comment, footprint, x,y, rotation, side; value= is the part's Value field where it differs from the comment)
C100 "LLS2W101MELZ" Nichicon_2200x3000_Snap 2495.39,3710.72 r270 top value=560uF
C101 "885012106018" 0603 4140,1380 r270 bottom value=2.2uF
C102 "885012206095" 0603 4260,1461.96 r180 bottom value=0.1uF
C103 "885012106018" 0603 5590,1122.6 r90 bottom value=2.2uF
C104 "885012206095" 0603 5450,1060 r0 bottom value=0.1uF
C105 "VY2471K29Y5SS63V7" VY2_750x500 365.03,902.22 r180 top value=470pF
C106 "VY2471K29Y5SS63V7" VY2_750x500 310,3950 r270 top value=470pF
C107 "ECQ-U2A334ML" CAPRR1500W80L1750T950H1750 389.19,2161.69 r180 top value=0.33uF
C108 "LLS2W101MELZ" Nichicon_2200x3000_Snap 2495.39,2780.72 r270 top value=560uF
C109 "AY2222M35Y5US63L7" AY2_950x500_Straight 3920.91,2153.3 r135 top value=2200pF
C110 "VY2471K29Y5SS63V7" VY2_750x500 722.08,902.22 r180 top value=470pF
C111 "VY2471K29Y5SS63V7" VY2_750x500 800,3950 r90 top value=470pF
C112 "B32671L0103J000" B32621_1300x600x1200 3932.48,3723.74 r270 top value=0.01uF
C113 "B32671L0103J000" B32621_1300x600x1200 3682.48,3723.74 r270 top value=0.01uF
C114 "B32671L0103J000" B32621_1300x600x1200 3682.7,2626.78 r270 top value=0.01uF
C115 "B32671L0103J000" B32621_1300x600x1200 3932.7,2626.78 r270 top value=0.01uF
C116 "B32671L0103J000" B32621_1300x600x1200 3682.48,3193.74 r270 top value=0.01uF
C117 "B32671L0103J000" B32621_1300x600x1200 3932.48,3193.74 r270 top value=0.01uF
C118 "VJ1206A220JXGAT5Z" 1206 3315.75,2320 r180 top value=22pF
C119 "GRM31A5C2J151JW01D" 1206 3315.75,2217.63 r0 top value=150pF
C120 "UMK316AB7475KL-T" 1206_190 4670,1282.87 r180 bottom value=4.7uF
C121 "UMK316AB7475KL-T" 1206_190 4670,1182.87 r180 bottom value=4.7uF
C122 "UMK316AB7475KL-T" 1206_190 4670,1082.87 r180 bottom value=4.7uF
C123 "UMK316AB7475KL-T" 1206_190 4670,982.87 r180 bottom value=4.7uF
C124 "25SEK470M" FR_1000x2000 5098.71,706.07 r0 top value=470uF
C125 "25SEK470M" FR_1000x2000 4648.71,706.07 r180 top value=470uF
C126 "25SEK470M" FR_1000x2000 4648.71,280 r180 top value=470uF
C127 "25SEK470M" FR_1000x2000 5098.71,280 r0 top value=470uF
C128 "UMK316AB7475KL-T" 1206_190 3758.84,82.62 r0 bottom value=4.7uF
C129 "0805YD105KAT2A" 0805_HV 1320,2150.88 r270 bottom value=1uF
C130 "C1206C225K4RACTU" 1206 3298.22,2409.95 r0 bottom value=2.2uF
C131 "C0603C470J5GACTU" 0603 2518.41,617.71 r0 top value=47pF
C132 "GRM155R61E104KA87D" 0402 2505.47,828.3 r180 top value=0.1uF
C133 "C1206C104K5RACTU" 1206 2879.33,901.06 r180 top value=0.1uF
C134 "GRM188R61C475KAAJ" 0603 3328.22,1956.33 r90 bottom value=4.7uF
C135 "GRM188R61C475KAAJ" 0603 3388.22,1956.33 r90 bottom value=4.7uF
C136 "GRM155R71H103KA88D" 0402 2700.63,1274.98 r270 top value=0.01uF
C137 "GRM155R61C333KA01D" 0402 2619.33,1251.06 r180 top value=0.033uF
C138 "06035A220JAT2A" 0603 3083.06,1954.52 r270 bottom value=22pF
C139 "GRM188R61C475KAAJ" 0603 3102.08,2487.63 r180 bottom value=4.7uF
C140 "GRM188R61C475KAAJ" 0603 3102.08,2547.63 r180 bottom value=4.7uF
C141 "GRM188R61C475KAAJ" 0603 3102.08,2607.63 r180 bottom value=4.7uF
C142 "C0603C474Z8VACTU" 0603 2922.08,2257.63 r270 bottom value=0.47uF
C143 "GRM188R71E272KA01D" 0603 3022.08,1954.52 r270 bottom value=2700pF
C144 "GRM1885C1H470FA01J" 0603 3143.06,1954.52 r270 bottom value=47pF
C145 "GRM188R71H221KA01D" 0603 3203.06,1954.52 r270 bottom value=220pF
C146 "06035A2R2CAT2A" 0603 2962.08,1954.51 r270 bottom value=2.2pF
C147 "GRM1885C1H470JA01D" 0603 2663.31,1190.98 r0 top value=47pF
C148 "GRM1885C1H470JA01D" 0603 2684.96,1046.39 r90 top value=47pF
C149 "08053C104JAT2A" 0805_HV 2811.49,1185.44 r0 bottom value=0.1uF
C150 "08053C104JAT2A" 0805_HV 2811.49,1097.59 r0 bottom value=0.1uF
C151 "225CKE450MJM" CKE_800x1150 1903.59,2096.22 r0 top value=2.2uF
C152 "C1206C103KARACTU" 1206 1900.52,1997.49 r0 bottom value=0.01uF
C153 "ECA-1EHG101" NHG_630x1120 2244.95,1296.33 r0 top value=100uF
C154 "08053C104KAT2A" 0805_HV 2247.93,1155.59 r0 bottom value=0.1uF
C155 "GRM155R71H103KA88D" 0402 3049.83,1314.61 r270 top value=0.01uF
C156 "GCM155R71H223KA55D" 0402 3127.87,1292.49 r0 top value=0.022uF
C157 "885012206040" 0603 2658.83,2013.85 r180 top value=0.01uF
C158 "06035C104KAT2A" 0603 2337.47,2092.54 r90 bottom value=0.1uF
C159 "GRM1555C1H470JA01D" 0402 3049.83,1214.61 r270 top value=47pF
C160 "GRM1885C1H470JA01D" 0603 3055.47,1051.06 r90 top value=47pF
C161 "06035C104KAT2A" 0603 3106.22,1179.98 r270 top value=0.1uF
C162 "06035C104KAT2A" 0603 3124.92,1051.06 r90 top value=0.1uF
C163 "35ZL18MEFC5X7" ML_500x500 2480.52,2036.9 r270 top value=18uF
C164 "GRM188R6YA225KA12D" 0603 2210.52,2092.28 r270 top value=2.2uF
C165 "UMK316AB7475KL-T" 1206_190 5090,800 r180 bottom value=4.7uF
C166 "UMK316AB7475KL-T" 1206_190 5090,900 r180 bottom value=4.7uF
C167 "UMK316AB7475KL-T" 1206_190 5090,1000 r180 bottom value=4.7uF
C168 "UMK316AB7475KL-T" 1206_190 5090,1097.59 r180 bottom value=4.7uF
CCset "5000" Keystone5000 2598.66,169.78 r90 top
CVset "5000" Keystone5000 2897.35,169.78 r180 top
D100 "GBU8J-BP" GBU 1618.73,3211.19 r270 top value=420V
D101 "MMDL914-TP" SOD-323 3390,3073.15 r180 bottom value=100V
D102 "STPS41L60CT" TO-220AB 3730,1256.91 r270 top value=60V
D103 "MMSZ4699T1G" SOD-123 1160,2146.33 r180 bottom value=12V
D104 "BAS316,115" sod-323 1110,1950 r90 bottom value=100V
D105 "MMDL914-TP" SOD-323 3080,3080 r180 bottom value=100V
D106 "STPS41L60CT" TO-220AB 6010,1260 r90 top value=60V
D107 "ES1JAF" SMAF 3242.08,2597.65 r90 bottom value=600V
D108 "MMSZ5231BS-7-F" SOD-323 2535.47,836.92 r180 bottom value=5.1V
D109 "SS110-TP" SMA 2005.64,1306.33 r90 top value=100V
D110 "1SMB5954BT3G" SMB 1700.52,1902.28 r90 bottom value=160V
D111 "BAT54A-7-F" SOT-23 2875.47,1400 r90 top value=30V
D112 "US1M-13-F" SMA 1789.1,1812.28 r0 top value=1.7V
D113 "BAS20HT1G" sod-323 2330.52,2032.56 r270 top
F100 "37216300001" FUSE_372 182.11,1630 r90 top
H100 "532602B02500G" Aavid_532602B02500G 1498.22,3211.19 r270 top
H101 "513302B02500G" 531202 5830,1268.89 r90 top
H102 "513302B02500G" 531202 3225.43,3299.42 r90 top
H103 "513302B02500G" 531202 3906.65,1256.91 r270 top
J100 "1-1318301-3" TE_1-1318301-3 533.62,1196.61 r180 top
J101 "ED120/4DS" On-Shore_ED120_4DS 3758.84,176.44 r0 top
J102 "923345-05-C" 923345-05-C 3022.08,2047.63 r0 top
K100 "G5LE-1-E-36-DC12" RELAY_875 1226.79,2045.13 r90 top
L100 "744825605" WE-CMB_XL 545.62,3052.98 r90 top value=5mH
L101 "61219" FP-61219_SMT_36MM0_34MM0-MFG 4908.53,3380.72 r0 top
LOGO100 "DANGER HIGH VOLTAGE" IEC_HighVoltage_Small 490,690.11 r0 top
LOGO101 "CAUTION HOT SURFACE" IEC_HotSurface_Small 250,695.11 r0 top
Logo102 "Pb-Free Symbol" Pb-Free_Overlay_Medium 245.5,415.11 r0 top
Logo103 "WEEE logo" WEEE_Minimum 488,416.41 r0 top
Logo104 "FCC disclaimer" FCC_disclaimer 1262.14,-1530 r270 top
PSON "5000" Keystone5000 2100,169.78 r180 top
Q100 "CSD19505KCS" KCS0003B 4070,1255.59 r180 top value=80V
Q101 "IPP60R090CFD7XKSA1" TO-220FP 3395.43,3299.74 r90 top value=650V
Q102 "FMMT718TA" SOT-23 3395.43,2957.24 r270 bottom value="20 V"
Q103 "IPP60R090CFD7XKSA1" TO-220FP 3055.43,3299.74 r270 top value=650V
Q104 "FMMT718TA" SOT-23 3120,2963.7 r270 bottom value="20 V"
Q105 "CSD19505KCS" KCS0003B 5660,1260 r0 top value=80V
Q106 "SI2309CDS" SOT-23 2658.83,1963.85 r270 bottom value=-60V
Q107 "2N7002-7-F" SOT-23 2522.14,1350 r90 bottom value=60V
R100 "CRCW12064K99FKEA" 1206 4260,1230 r0 bottom value=4.99k
R101 "CRCW12064K99FKEA" 1206 5480,1280 r180 bottom value=4.99k
R102 "CRCW12061M00FKEA" 1206 2615.39,3800.72 r90 bottom value=1.00Meg
R103 "CRCW04020000Z0ED" 0402 4190,1141.06 r0 bottom value=0
R104 "CRCW04020000Z0ED" 0402 5560,1360 r180 bottom value=0
R105 "CRCW12061M00FKEA" 1206 2615.39,3600.72 r90 bottom value=1.00Meg
R106 "CRCW1206499KFKEA" 1206 239.19,2161.69 r180 bottom value=499k
R107 "CRCW12061M00FKEA" 1206 2378.22,2866.33 r90 bottom value=1.00Meg
R108 "CRCW1206499KFKEA" 1206 519.19,2161.69 r180 bottom value=499k
R109 "CRCW12061M00FKEA" 1206 2378.22,2666.33 r90 bottom value=1.00Meg
R110 "CRCW060310R0FKEA" 0603 3289.25,3040 r90 bottom value=10.0
R111 "CRCW060320K0FKEA" 0603 3328.5,3306.33 r270 bottom value=20.0k
R112 "CRCW1206150RJNEA" 1206 1223.62,1966.94 r90 bottom value=150
R113 "CRCW1206150RJNEA" 1206 1330,1966.94 r90 bottom value=150
R114 "CRCW060310R0FKEA" 0603 3020,2976.58 r90 bottom value=10.0
R115 "CRCW060320K0FKEA" 0603 3122.36,3296.33 r90 bottom value=20.0k
R116 "PMR50HZPFV2L00" 2010 3925.58,382.04 r270 bottom value=0.002
R117 "PMR50HZPFV2L00" 2010 4073.22,382.04 r270 bottom value=0.002
R118 "CRCW06032R20JNEA" 0603 3118.22,2676.33 r0 bottom value=2.2
R119 "RC0603FR-074R75L" 0603 2551.22,524.45 r270 top value=4.75
R120 "RC0603FR-074R75L" 0603 2486.88,524.45 r270 top value=4.75
R121 "CRCW060310K0FKEA" 0603 2425.47,986.96 r90 top value=10.0k
R122 "CRCW06030000Z0EA" 0603 3428.22,2087.25 r0 bottom value=0
R123 "CRCW12064M99FKEA" 1206 2798.22,1856.33 r180 top value=4.99Meg
R124 "CRCW12064M99FKEA" 1206 2918.22,2142.66 r180 top value=4.99Meg
R125 "CRCW1206866KFKEA" 1206 3072.08,2405.54 r0 bottom value=866k
R126 "CRCW12064M99FKEA" 1206 3120.15,2142.66 r180 top value=4.99Meg
R127 "CRCW12061K00FKEA" 1206 2518.38,1151.06 r270 top value=1.00k
R128 "CRCW120620R5FKEA" 1206 2518.38,953.98 r270 top value=20.5
R129 "CRCW060340R2FKEA" 0603 3083.06,1954.53 r90 top value=40.2
R130 "CRCW04021K00FKED" 0402 2619.33,1301.06 r180 top value=1.00k
R131 "CRCW0603750KFKEA" 0603 2862.08,2257.63 r90 bottom value=750k
R132 "CRCW0603249KFKEA" 0603 3261.68,1946.33 r90 bottom value=249k
R133 "CRCW06036K65FKEA" 0603 2962.08,1954.51 r90 top value=6.65k
R134 "RC0603FR-0739KL" 0603 2684.96,1046.39 r270 bottom value=39.0k
R135 "RC0603FR-0739KL" 0603 2625.47,1046.66 r270 top value=39.0k
R136 "CRCW080510K0FKEA" 0805_HV 3287.08,1352.76 r0 bottom value=10.0k
R137 "CRCW06035K36FKEA" 0603 2813.05,1262.87 r180 bottom value=5.36k
R138 "CRCW060315K0FKEA" 0603 2798.64,1021.06 r180 bottom value=15.0k
R139 "CRCW06031M00FKEA" 0603 2674.75,89.78 r180 bottom value=1.00Meg
R140 "CRCW06032K00JNEA" 0603 2248.22,1232.15 r180 bottom value=2.0k
R141 "CRCW12060000Z0EA" 1206 3279.29,1823.46 r0 bottom value=0
R142 "RC1206FR-0749R9L" 1206 3305.47,1238.23 r0 bottom value=49.9
R143 "CRCW040220K0FKED" 0402 3127.87,1339.74 r0 top value=20.0k
R144 "RC0603FR-071RL" 0603 2305.98,1936.65 r180 top value=1.00
R145 "CRCW060318K7FKEA" 0603 3133.48,1234.74 r0 bottom value=18.7k
R146 "CRCW060360K4FKEA" 0603 2305.98,1908.11 r180 bottom value=60.4k
R147 "CRCW120620K0FKEA" 1206 2346.53,1397.24 r0 bottom value=20.0k
R148 "CRCW0603100KFKEA" 0603 2658.83,2076.69 r0 top value=100k
R149 "CRCW06032K43FKEA" 0603 2236.83,2270.2 r0 bottom value=2.43k
R150 "ERJ-3EKF4752V" 0603 2522.12,1461.96 r180 bottom value=47.5k
R151 "CRCW060318K7FKEA" 0603 3169.76,1179.98 r90 top value=18.7k
R152 "ERJ-8ENF3902V" 1206 3127.87,885.38 r270 top value=39.0k
R153 "CRCW060316K5FKEA" 0603 2367.97,1979.11 r180 bottom value=16.5k
R154 "CRCW06031K00JNEA" 0603 2520,1175.87 r180 bottom value=1.0k
R155 "CRCW060318K7FKEA" 0603 3248.38,1179.98 r90 top value=18.7k
R156 "RC0603FR-072K49L" 0603 3134.76,1164.74 r180 bottom value=2.49k
R157 "CRCW060315K0FKEA" 0603 3195.47,1051.06 r270 top value=15.0k
R158 "CRCW06031M00FKEA" 0603 2976.66,90 r180 bottom value=1.00Meg
R159 "CRCW0603100KFKEA" 0603 2518.52,1240 r0 bottom value=100k
RT100 "B59751B0120A070" TDK_B751 1010,1560 r270 top value="50 ohm"
SGND "5001" Keystone5001 3046.72,169.78 r180 top value=Black
SGND "5001" Keystone5001 4268.84,176.44 r0 top
SGND "5001" Keystone5001 2248,169.78 r180 top value=Black
SGND "5001" Keystone5001 2750.42,169.78 r90 top value=Black
T100 "500µH" FP-61201_SMT_XFRMR_44MM0_34MM0-MFG 4868.22,1806.33 r90 top
T101 "RLTI-1352" FP-RLTI-1352_PTH_XFRMR_0IN42_0IN48-MFG 2172.06,1668.11 r270 top
U100 "UCC24612-1DBVR" DBV0005A_N 4260,1356.78 r0 bottom
U101 "UCC24612-1DBVR" DBV0005A_N 5470,1160 r180 bottom
U102 "UCC256403" DDB0014A 3162.08,2197.63 r90 bottom
U103 "INA180A2IDBV" DBV0005A_N 2518.41,724.13 r0 top
U104 "LM324DR" D0014A_N 2875.47,1136.96 r0 top
U105 "VO618A" DIP-4 3292.08,1593.46 r90 top
U106 "UCC28910DR" D0007A_N 2188.98,2088.11 r270 bottom
U107 "PC817X4NSZ0F" DIP762W60P254L460H350Q4B 2560.52,1682.28 r90 top
Vout "5000" Keystone5000 3268.84,176.44 r0 top

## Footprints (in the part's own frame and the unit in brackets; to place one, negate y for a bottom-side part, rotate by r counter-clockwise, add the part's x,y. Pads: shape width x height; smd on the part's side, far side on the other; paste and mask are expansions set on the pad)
0402 [mm] "0402 from SM-752 data"
  rect 0.8x0.6 smd: 1(-0.6,0) 2(0.6,0)
  silkscreen extent -1.22,-0.52 1.22,0.52, body extent -0.55,-0.3 0.55,0.3, height 0.6
0603 [mm] "0603 from SM-752 data"
  rect 1x0.95 smd: 1(-0.8,0) 2(0.8,0)
  silkscreen extent -1.52,-0.69 1.52,0.69, body extent -0.87,-0.47 0.87,0.47, height 1
0805_HV [mil] "0805 with 30mil clearance between pads"
  rect 50x63 smd: 1(-40,0) 2(40,0)
  silkscreen extent -74,-40 74,40, body extent -43,-29 43,29, height 57
1206 [mm] "1206 from SM-752 data"
  rect 1.3x1.85 smd: 1(-1.45,0) 2(1.45,0)
  silkscreen extent -2.4,-1.21 2.4,1.21, body extent -1.7,-0.9 1.7,0.9, height 1.35
1206_190 [mm] "1206_190"
  rect 1.1x1.6 smd: 1(-1.7,0) 2(1.7,0)
  silkscreen extent -0.9,-1 0.9,1, body extent -1.75,-0.95 1.75,0.95, height 1.9
2010 [mm] "Chip Capacitor, Body 5.08x2.54mm, IPC Medium Density"
  rect 1.6x2.7 smd: 1(-2.3,0) 2(2.3,0)
  silkscreen extent -3.42,-1.65 3.42,1.65, body extent -2.73,-1.45 2.73,1.45, height 1.66
531202 [mm] "TH, 2-Leads, Body 34.92x12.7mm, Pin Spacing 25.4mm"
  round 3.2 hole 2.67: 1(-12.7,0) 2(12.7,0)
  silkscreen extent -17.46,-6.35 17.46,6.35, body extent -17.46,-6.35 17.46,6.35, height 50.8
923345-05-C [mil] "Wire Jumper 500mil"
  round 60 hole 38: 1(-250,0) 2(250,0)
  body extent -263,-33 263,33, height 71
Aavid_532602B02500G [mm] "Heat Sink, TO-220 Vertical"
  round 3.2 hole 2.67: 1(-12.7,0) 2(12.7,0)
  silkscreen extent -20.96,-12.7 20.96,12.7, body extent -20.95,-12.7 20.96,12.7, height 38.1
AY2_950x500_Straight [mm] "TH, 2-Leads, 9.5x5mm, Pin Spacing 7.5mm"
  round 1.4 hole 0.9: 1(-3.75,1.6) 2(3.75,-1.6)
  silkscreen extent -4.75,-2.5 4.75,2.5, body extent -4.74,-2.5 4.75,2.5, height 12.5
B32621_1300x600x1200 [mm] "TH, 2-Leads, Body 13x6mm, Pin Spacing 10mm"
  round 1.275 hole 0.85: 1(-5,0) 2(5,0)
  silkscreen extent -6.5,-3 6.5,3, body extent -6.5,-3 6.5,3, height 12
CAPRR1500W80L1750T950H1750 [mm] "PANASONIC"
  round 1.7 hole 1.069: 1(-7.5,0) 2(7.5,0)
  silkscreen extent -9,-5 9,5, body extent -9,-5 9,5, height 18
CKE_800x1150 [mm] "TH, 2-Leads, Dia 8mm, Pin Spacing 3.5mm"
  rect 1.25x1.25 hole 0.75: 1(-1.75,0)
  round 1.25 hole 0.75: 2(1.75,0)
  silkscreen extent -4.25,-4.25 4.25,4.25, body extent -4.25,-4.25 4.26,4.25, height 13.01
D0007A_N [mm] "SOIC, 7-Leads, Body 4.9x3.9mm, Pitch 1.27mm, IPC Medium Density"
  oval 1.45x0.6 smd: 1(-2.725,1.905) 2(-2.725,0.635) 3(-2.725,-0.635) 4(-2.725,-1.905) 5(2.725,-1.905) 6(2.725,-0.635) 8(2.725,1.905)
  silkscreen extent -3.32,-2.5 1.1,2.52, body extent -3.01,-2.45 3.01,2.45, height 1.75
D0014A_N [mm] "SOIC, 14-Leads, Body 8.7x3.9mm, Pitch 1.27mm, IPC Medium Density"
  oval 1.45x0.6 smd: 1(-2.725,3.81) 2(-2.725,2.54) 3(-2.725,1.27) 4(-2.725,0) 5(-2.725,-1.27) 6(-2.725,-2.54) 7(-2.725,-3.81) 8(2.725,-3.81) 9(2.725,-2.54) 10(2.725,-1.27) 11(2.725,0) 12(2.725,1.27) 13(2.725,2.54) 14(2.725,3.81)
  silkscreen extent -3.3,-4.4 0.9,4.4, body extent -3.02,-4.32 3.02,4.32, height 1.6
DBV0005A_N [mm] "SOT23, 5-Leads, Body 2.9x1.6mm, Pitch 0.95mm, Lead Span 2.8mm, IPC Medium Density"
  rrect17% 1x0.6 smd: 1(-1.375,0.95) 2(-1.375,0) 3(-1.375,-0.95) 4(1.375,-0.95) 5(1.375,0.95)
  silkscreen extent -0.25,-1.55 0.25,1.55, body extent -1.42,-1.46 1.42,1.46, height 1.09
DDB0014A [mm] "SMD, 14-Leads, Body 3.9x9.9mm, Pitch 1.27mm"
  rrect17% 1.55x0.6 smd: 1(-2.7,4.445) 3(-2.7,1.905) 4(-2.7,0.635) 5(-2.7,-0.635) 6(-2.7,-1.905) 7(-2.7,-3.175) 8(-2.7,-4.445) 9(2.7,-4.445) 10(2.7,-3.175) 11(2.7,-1.905) 12(2.7,-0.635) 14(2.7,1.905) 15(2.7,3.175) 16(2.7,4.445)
  silkscreen extent -3.5,-5 2,5, body extent -3.01,-4.95 3.01,4.95, height 1.75
DIP762W60P254L460H350Q4B [mm] "LITE-ON"
  rrect8% 1.2x1.2 hole 0.85: 1(-3.81,1.27)
  round 1.2 hole 0.85: 2(-3.81,-1.27) 3(3.81,-1.27) 4(3.81,1.27)
  silkscreen extent -4.29,-2.29 3.25,2.3, body extent -3.94,-2.29 3.94,2.3, height 4.3
DIP-4 [mm] "DIP, 4-Leads, Body 6.86x4.83mm, Pitch 2.54mm"
  rect 1.15x1.15 hole 0.65: 1(-3.81,1.27)
  round 1.15 hole 0.65: 2(-3.81,-1.27) 3(3.81,-1.27) 4(3.81,1.27)
  silkscreen extent -4,-2.41 3.43,2.52, body extent -4.02,-2.41 4.02,2.41, height 5.59
FCC_disclaimer [mil]
FP-61201_SMT_XFRMR_44MM0_34MM0-MFG [mm]
  rrect3% 4x4 smd paste+0 mask+0: 1(20.14,-10.16) 5(20.14,10.16)
  rrect2% 4.2x6.2 smd paste+0 mask+0: 6(-20.04,9.23) 7(-20.04,0) 8(-20.04,-9.23)
  silkscreen extent -22,-17 22.82,17, body extent -22.24,-17.1 22.24,17.1, height 0.25
FP-61219_SMT_36MM0_34MM0-MFG [mm]
  rrect2% 4.5x4.5 smd paste+0 mask+0: 1(-15.75,9) 2(-15.75,-9)
  silkscreen extent -18,-17 18,17, body extent -18.1,-17.1 18.1,17.1, height 0.25
FP-RLTI-1352_PTH_XFRMR_0IN42_0IN48-MFG [mm]
  rrect9% 1.15x1.15 hole 0.65 paste-1000 mask+0: 1(-4.064,3.734)
  round 1.15 hole 0.65 paste-1000 mask+0: 2(-4.064,1.245) 3(-4.064,-1.245) 4(-4.064,-3.734) 5(4.064,-3.734) 6(4.064,-1.245) 7(4.064,1.245) 8(4.064,3.734)
  silkscreen extent -6.01,-6.1 5.33,6.1, body extent -5.43,-6.2 5.43,6.2, height 0.25
FR_1000x2000 [mm] "PANASONIC"
  rect 1.55x1.55 hole 0.85: 1(-2.5,0)
  round 1.55 hole 0.85: 2(2.5,0)
  silkscreen extent -5.26,-5.26 5.26,5.26, body extent -5.21,-5.24 5.24,5.24, height 22.01
FUSE_372 [mm] "LITTELFUSE"
  round 1.5 hole 1: 1(-2.54,0) 2(2.54,0)
  silkscreen extent -4.25,-4.25 4.25,4.25, body extent -4.25,-4.25 4.25,4.25, height 8
GBU [mm] "Comchip / Diodes Inc diode bridge"
  round 2 hole 1.5: 1(-7.62,0) 2(-2.54,0) 3(2.54,0) 4(7.62,0)
  silkscreen extent -11.15,-2.28 11.15,1.28, body extent -11.15,-2.28 11.15,1.28, height 21.55
IEC_HighVoltage_Small [mil]
  silkscreen extent -107,-88 107,97
IEC_HotSurface_Small [mil]
  silkscreen extent -107,-93 107,92
KCS0003B [mm] "Flange Mount, 3-Leads, Body 10.16x4.51mm, Pitch 2.54mm"
  rrect25% 1.6x1.6 hole 1: 1(0,2.54)
  round 1.6 hole 1: 2(0,0) 3(0,-2.54)
  silkscreen extent -1.71,-5.08 2.86,5.08, body extent -1.71,-5.09 2.86,5.08, height 18.63
Keystone5000 [mil] "For Keystone 500x miniature loop terminals"
  round 80 hole 40: 1(0,0)
  silkscreen extent -52,-52 52,52, body extent -49,-49 49,49, height 182
Keystone5001 [mil] "For Keystone 500x miniature loop terminals"
  round 80 hole 40: 1(0,0)
  silkscreen extent -52,-52 52,52, body extent -49,-49 49,49, height 182
ML_500x500 [mm] "Rubycon"
  rect 1.2x1.2 hole 0.711: 1(-1,0)
  round 1.2 hole 0.711: 2(1,0)
  silkscreen extent -2.75,-2.75 2.75,2.75, body extent -2.73,-2.75 2.75,2.75, height 6.51
NHG_630x1120 [mm] "TH, 2-Leads, Dia 6.3mm, Pin Spacing 2.5mm"
  rect 1.3x1.3 hole 0.8: 1(-1.25,0)
  round 1.3 hole 0.8: 2(1.25,0)
  silkscreen extent -3.4,-3.4 3.4,3.4, body extent -3.37,-3.39 3.4,3.39, height 12.21
Nichicon_2200x3000_Snap [mm]
  rrect3% 3x3 hole 2.2: 1(-5,0)
  round 3 hole 2.2: 2(5,0)
  silkscreen extent -11.6,-11.6 11.6,11.6, body extent -11.5,-11.5 11.51,11.5, height 32.01
On-Shore_ED120_4DS [mm] "ONSHORE"
  rrect5% 2x2 hole 1.25: 1(-7.62,0)
  round 2 hole 1.25: 2(-2.54,0) 3(2.54,0) 4(7.62,0)
  silkscreen extent -10.68,-4 10.16,5, body extent -10.86,-4 10.16,5, height 13
Pb-Free_Overlay_Medium [mil]
  silkscreen extent -95,-95 95,95
RELAY_875 [mm] "TH, 5-Leads, Body 21x16mm"
  rect 1.8x1.8 hole 1.3: 1(-6,7.1)
  round 1.8 hole 1.3: 2(6,7.1) 3(0,-7.1) 4(-6,-5.1) 5(6,-5.1)
  silkscreen extent -8.5,-9.15 8,11.85, body extent -8,-9.15 8,11.85, height 20.6
SMA [mm] "Molded Diode, 2-Leads, Body 4.3x2.6mm, IPC Medium Density, based on OnSemi component dimensions and land pattern"
  rect 2x2 smd: 1(-2,0) 2(2,0)
  silkscreen extent -3.66,-1.57 2.79,1.57, body extent -2.6,-1.3 2.6,1.3, height 2.42
SMAF [mm] "SMD, 2-Leads, Body 3.8x2.5mm"
  rect 1.24x1.89 smd: 1(-2.04,0) 2(2.04,0)
  silkscreen extent -3.4,-1.3 2.8,1.3, body extent -2.35,-1.25 2.35,1.25, height 1
SMB [mil] "Molded Diode, 2-Leads, Body 5.4x3.6mm, IPC Medium Density, based on OnSemi component dimensions"
  rect 85x107.99 smd: 1(-87.01,0) 2(87.01,0)
  silkscreen extent -155,-82 125,82, body extent -106,-71 106,71, height 91
SOD-123 [mm] "On Semi recommended land pattern"
  rect 0.915x1.22 smd: 1(-1.637,0) 2(1.637,0)
  silkscreen extent -2.74,-1.17 2.03,1.17, body extent -1.93,-0.9 1.93,0.9, height 1.35
SOD-323 [mm] "NXP recommended land pattern"
  rect 0.6x0.6 smd paste-0.05: 1(-1.1,0) 2(1.1,0)
  silkscreen extent -2.06,-0.86 1.53,0.86, body extent -1.3,-0.67 1.3,0.68, height 1.1
sod-323 [mm] "NXP recommended land pattern"
  rect 0.6x0.6 smd paste-0.05: 1(-1.1,0) 2(1.1,0)
  silkscreen extent -2.06,-0.86 1.53,0.86, body extent -1.3,-0.67 1.3,0.68, height 1.1
SOT-23 [mm] "SOT23, 3-Leads, Body 2.9x1.3mm, Pitch 0.95mm, Lead Span 2.5mm, IPC Medium Density"
  rrect50% 1x0.6 smd: 1(-1.2,0.95) 2(-1.2,-0.95) 3(1.2,0)
  silkscreen extent -1.62,-1.5 0.7,1.5, body extent -1.16,-1.45 1.21,1.45, height 1
TDK_B751 [mm] "TH, 2-Leads, Dia 12.5mm, Pin Spacing 5mm"
  round 1.35 hole 0.85: 1(0,2.5) 2(0,-2.5)
  silkscreen extent -3.5,-6.25 3.5,6.25, body extent -3.48,-6.2 3.48,6.25, height 16.49
TE_1-1318301-3 [mm] "TE"
  rect 2.9x2.9 hole 2.15: 1(-7.925,0)
  round 2.9 hole 2.15: 2(0,0) 3(7.925,0)
  silkscreen extent -10.13,-4.53 10.08,4.46, body extent -9.87,-4.28 9.87,4.22, height 10.72
TO-220AB [mil] "Copied from Altium's version of TO3B"
  rrect25% 76x118.11 hole 50: 1(-100,0)
  oval 76x118.11 hole 50: 2(0,0) 3(100,0)
  silkscreen extent -221,-59 221,126, body extent -221,-59 221,126, height 765
TO-220FP [mm] "FM, Body 10.4x4.6mm, Pitch 2.55mm"
  rrect50% 1.95x1.95 hole 1.3: 1(-2.55,0)
  round 1.95 hole 1.3: 2(0,-2.54) 3(2.55,0)
  silkscreen extent -5.1,-1.5 5.08,3, body extent -5.09,-1.5 5.09,3, height 19.41
VY2_750x500 [mm] "Vishay"
  round 1.5 hole 0.889: 1(-3.75,1.875) 2(3.75,-1.875)
  silkscreen extent -3.75,-2.5 3.75,2.5, body extent -4.05,-2.5 4.05,2.5, height 10.49
WE-CMB_XL [mm] "Wurth"
  rect 2x2 hole 1.3: 1(-12.5,7.5)
  round 2 hole 1.3: 6(12.5,7.5) 7(12.5,-7.5) 12(-12.5,-7.5)
  silkscreen extent -15,-10.18 15,9.3, body extent -15.25,-10.5 15.25,10.5, height 35
WEEE_Minimum [mil] "WEEElie bin"
  silkscreen extent -95,-172 99,104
